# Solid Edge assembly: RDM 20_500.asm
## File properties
Title: Zylinder
Author: ahadarics
Template: iso metric assembly.asm
Last saved by: ahadarics
Revision: 30
Application: Solid Edge
Username: ahadarics
Dokumentum tartalom típus: 1
Document Number: RDM 20/500
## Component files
Kit_2.par
Profilrohr.par
Kolbenstange.par
Kit_1.par
Mutter_1.par
Mutter_2.par
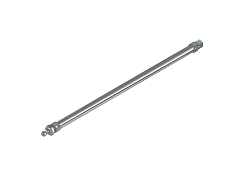
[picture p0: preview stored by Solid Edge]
